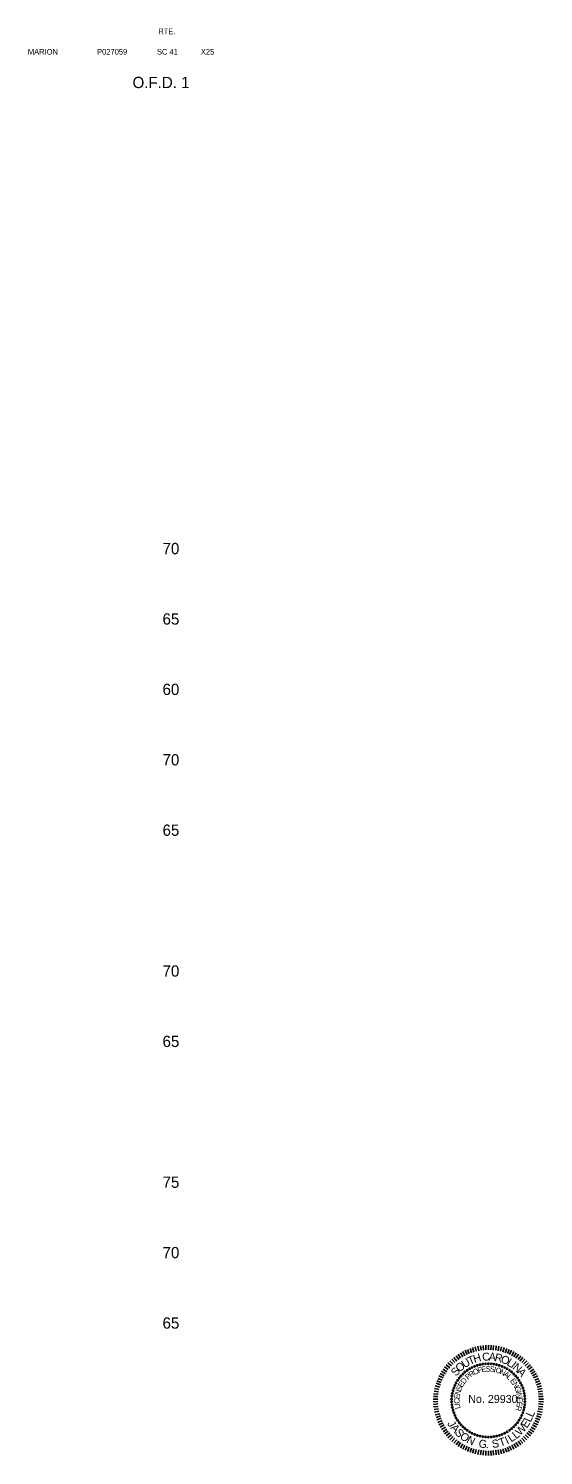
# Model space of a CAD drawing. Extents: x 1001 to 1184, y 1001 to 1102.
# Drawn here: x 1147.4 to 1184, y 1001 to 1102.3 of the extents above; entities that cross this region are included whole.
import ezdxf

# ---------------------------------------------------------------- set-up
doc = ezdxf.new("R2010")
doc.units = 0
for name, color, linetype in [('RD_HC_Cl', 7, 'Continuous'), ('RD_SHT_TX', 7, 'Continuous'), ('RD_TX_PEShield', 7, 'Continuous'), ('RD_XS_TX_Elev_EX', 7, 'Continuous')]:
    doc.layers.add(name, color=color, linetype=linetype)

# ---------------------------------------------------------------- blocks, each defined once
blk = doc.blocks.new('STILLWELL')
at = {"layer": 'RD_TX_PEShield'}
for p, q in [((-21.1, 28.1), (-23, 30.7)), ((-19.7, 29.1), (-21.5, 31.8)), ((-18.2, 30), (-19.9, 32.8)), ((-16.7, 30.8), (-18.2, 33.7)), ((-15.1, 31.6), (-16.5, 34.6)), ((-13.6, 32.3), (-14.8, 35.3)), ((-11.9, 32.9), (-13, 36)), ((-10.3, 33.4), (-11.2, 36.6)), ((-8.6, 33.9), (-9.4, 37.1)), ((-6.9, 34.3), (-7.5, 37.5)), ((-5.2, 34.6), (-5.7, 37.8)), ((-3.5, 34.8), (-3.8, 38)), ((-1.8, 34.9), (-1.9, 38.2)), ((0, 34.9), (0, 38.2)), ((1.7, 34.9), (1.9, 38.2)), ((3.4, 34.8), (3.7, 38)), ((5.2, 34.6), (5.6, 37.8)), ((6.9, 34.3), (7.5, 37.5)), ((8.6, 33.9), (9.3, 37.1)), ((10.2, 33.4), (11.2, 36.6)), ((11.9, 32.9), (13, 36)), ((13.5, 32.3), (14.7, 35.3)), ((15.1, 31.6), (16.5, 34.6)), ((16.6, 30.8), (18.2, 33.7)), ((18.2, 30), (19.8, 32.8)), ((19.6, 29.1), (21.4, 31.8)), ((21.1, 28.1), (23, 30.7)), ((-29.5, 19.4), (-32.2, 21.3)), ((-28.5, 20.9), (-31.1, 22.8)), ((-27.4, 22.2), (-29.9, 24.3)), ((-26.3, 23.5), (-28.7, 25.7)), ((-25.1, 24.7), (-27.4, 27.1)), ((-23.8, 25.9), (-26, 28.4)), ((-22.5, 27), (-24.5, 29.6)), ((22.4, 27), (24.5, 29.6)), ((23.8, 25.9), (25.9, 28.4)), ((25, 24.7), (27.3, 27.1)), ((26.2, 23.5), (28.6, 25.7)), ((27.4, 22.2), (29.9, 24.3)), ((28.5, 20.9), (31.1, 22.8)), ((29.5, 19.4), (32.2, 21.3)), ((-34.1, 10.2), (-37.2, 11.2)), ((-33.6, 11.8), (-36.6, 12.9)), ((-32.9, 13.4), (-35.9, 14.7)), ((-32.2, 15), (-35.1, 16.4)), ((-31.4, 16.5), (-34.2, 18.1)), ((-30.5, 18), (-33.3, 19.7)), ((30.4, 18), (33.2, 19.7)), ((31.3, 16.5), (34.2, 18.1)), ((32.1, 15), (35.1, 16.4)), ((32.9, 13.4), (35.9, 14.7)), ((33.5, 11.8), (36.6, 12.9)), ((34.1, 10.2), (37.2, 11.2)), ((-35.9, -0.1), (-39.2, 0)), ((-35.8, 1.7), (-39.1, 1.9)), ((-35.6, 3.4), (-38.9, 3.8)), ((-35.4, 5.1), (-38.6, 5.7)), ((-35.1, 6.8), (-38.2, 7.5)), ((-34.6, 8.5), (-37.8, 9.4)), ((34.6, 8.5), (37.7, 9.4)), ((35, 6.8), (38.2, 7.5)), ((35.3, 5.1), (38.5, 5.7)), ((35.6, 3.4), (38.8, 3.8)), ((35.7, 1.7), (39, 1.9)), ((35.8, -0.1), (39.1, 0)), ((-35.9, -1.8), (-39.2, -1.9)), ((-35.8, -3.5), (-39.1, -3.8)), ((-35.6, -5.3), (-38.9, -5.6)), ((-35.4, -7), (-38.6, -7.5)), ((-35.1, -8.7), (-38.2, -9.4)), ((35, -8.7), (38.2, -9.4)), ((35.3, -7), (38.5, -7.5)), ((35.6, -5.3), (38.8, -5.6)), ((35.7, -3.5), (39, -3.8)), ((35.8, -1.8), (39.1, -1.9)), ((-34.6, -10.4), (-37.8, -11.2)), ((-34.1, -12), (-37.2, -13)), ((-33.6, -13.6), (-36.6, -14.8)), ((-32.9, -15.3), (-35.9, -16.6)), ((-32.2, -16.8), (-35.1, -18.3)), ((-31.4, -18.4), (-34.2, -19.9)), ((-30.5, -19.9), (-33.3, -21.6)), ((30.4, -19.9), (33.2, -21.6)), ((31.3, -18.4), (34.2, -19.9)), ((32.1, -16.8), (35.1, -18.3)), ((32.9, -15.3), (35.9, -16.6)), ((33.5, -13.6), (36.6, -14.8)), ((34.1, -12), (37.2, -13)), ((34.6, -10.4), (37.7, -11.2)), ((-29.5, -21.3), (-32.2, -23.2)), ((-28.5, -22.7), (-31.1, -24.7)), ((-27.4, -24.1), (-29.9, -26.2)), ((-26.3, -25.4), (-28.7, -27.6)), ((-25.1, -26.6), (-27.4, -28.9)), ((-23.8, -27.8), (-26, -30.2)), ((-22.5, -28.9), (-24.5, -31.4)), ((-21.1, -29.9), (-23, -32.6)), ((21.1, -29.9), (23, -32.6)), ((22.4, -28.9), (24.5, -31.4)), ((23.8, -27.8), (25.9, -30.2)), ((25, -26.6), (27.3, -28.9)), ((26.2, -25.4), (28.6, -27.6)), ((27.4, -24.1), (29.9, -26.2)), ((28.5, -22.7), (31.1, -24.7)), ((29.5, -21.3), (32.2, -23.2)), ((-19.7, -30.9), (-21.5, -33.7)), ((-18.2, -31.8), (-19.9, -34.7)), ((-16.7, -32.7), (-18.2, -35.6)), ((-15.1, -33.5), (-16.5, -36.4)), ((-13.6, -34.1), (-14.8, -37.2)), ((-11.9, -34.8), (-13, -37.8)), ((-10.3, -35.3), (-11.2, -38.4)), ((-8.6, -35.8), (-9.4, -38.9)), ((-6.9, -36.1), (-7.5, -39.3)), ((-5.2, -36.4), (-5.7, -39.7)), ((-3.5, -36.6), (-3.8, -39.9)), ((-1.8, -36.8), (-1.9, -40)), ((0, -36.8), (0, -40.1)), ((1.7, -36.8), (1.9, -40)), ((3.4, -36.6), (3.7, -39.9)), ((5.2, -36.4), (5.6, -39.7)), ((6.9, -36.1), (7.5, -39.3)), ((8.6, -35.8), (9.3, -38.9)), ((10.2, -35.3), (11.2, -38.4)), ((11.9, -34.8), (13, -37.8)), ((13.5, -34.1), (14.7, -37.2)), ((15.1, -33.5), (16.5, -36.4)), ((16.6, -32.7), (18.2, -35.6)), ((18.2, -31.8), (19.8, -34.7)), ((19.6, -30.9), (21.4, -33.7))]:
    blk.add_line(p, q, dxfattribs=at)
for centre in [(-15, 20.4), (-13.3, 21.5), (-11.6, 22.4), (-9.8, 23.2), (-7.9, 23.9), (-6, 24.4), (-4, 24.8), (-2, 25), (0, 25.1), (2, 25), (3.9, 24.8), (5.9, 24.4), (7.8, 23.9), (9.7, 23.2), (11.5, 22.4), (13.3, 21.5), (15, 20.4), (-23.8, 9.7), (-22.9, 11.5), (-21.9, 13.2), (-20.7, 14.9), (-19.5, 16.4), (-18.1, 17.8), (-16.6, 19.2), (16.5, 19.2), (18, 17.8), (19.4, 16.4), (20.7, 14.9), (21.8, 13.2), (22.9, 11.5), (23.7, 9.7), (-26.1, 0.1), (-25.9, 2.1), (-25.6, 4), (-25.1, 6), (-24.5, 7.9), (24.5, 7.9), (25.1, 6), (25.5, 4), (25.8, 2.1), (26, 0.1), (-26.1, -1.9), (-25.9, -3.9), (-25.6, -5.9), (-25.1, -7.8), (-24.5, -9.7), (24.5, -9.7), (25.1, -7.8), (25.5, -5.9), (25.8, -3.9), (26, -1.9), (-23.8, -11.6), (-22.9, -13.4), (-21.9, -15.1), (-20.7, -16.7), (-19.5, -18.3), (-18.1, -19.7), (18, -19.7), (19.4, -18.3), (20.7, -16.7), (21.8, -15.1), (22.9, -13.4), (23.7, -11.6), (-16.6, -21), (-15, -22.2), (-13.3, -23.3), (-11.6, -24.3), (-9.8, -25.1), (-7.9, -25.8), (-6, -26.3), (-4, -26.7), (-2, -26.9), (0, -27), (2, -26.9), (3.9, -26.7), (5.9, -26.3), (7.8, -25.8), (9.7, -25.1), (11.5, -24.3), (13.3, -23.3), (15, -22.2), (16.5, -21)]:
    blk.add_circle(centre, 0.49, dxfattribs=at)
for s, height, rotation, p in [('T', 5.68, 23.5044, (-13.2, 24.1)), ('H', 5.68, 16.1357, (-9.9, 25.6)), ('C', 5.68, 4.076, (-4.2, 27.1)), ('A', 5.68, 355.3651, (0.1, 27.4)), ('R', 5.68, 347.3188, (4.1, 27.1)), ('O', 5.68, 338.6079, (8.3, 26.2)), ('S', 5.68, 49.6435, (-22.9, 15.8)), ('O', 5.68, 41.5972, (-20.4, 18.8)), ('U', 5.68, 32.2152, (-16.9, 21.8)), ('O', 3.92, 24.9735, (-10, 16.9)), ('F', 3.92, 15.9995, (-7.1, 18.3)), ('E', 3.92, 8.9511, (-4.7, 19)), ('S', 3.92, 1.2546, (-1.9, 19.4)), ('S', 3.92, 353.558, (0.8, 19.5)), ('I', 3.92, 345.8615, (3.5, 19.2)), ('O', 3.92, 342.6583, (4.7, 19)), ('N', 3.92, 333.6842, (7.7, 18)), ('L', 5.68, 329.226, (12.6, 24.4)), ('I', 5.68, 322.5218, (15.5, 22.8)), ('N', 5.68, 319.1729, (16.8, 21.8)), ('A', 5.68, 310.4621, (20.1, 19)), ('E', 3.92, 60.2341, (-18.5, 7.9)), ('D', 3.92, 52.5376, (-17.1, 10.3)), ('P', 3.92, 41.0022, (-14.5, 13.5)), ('R', 3.92, 33.3057, (-12.5, 15.3)), ('A', 3.92, 325.3521, (10.4, 16.7)), ('L', 3.92, 317.6555, (12.6, 15.1)), ('E', 3.92, 308.0396, (15.1, 12.8)), ('N', 3.92, 300.343, (16.8, 10.6)), ('C', 3.92, 92.2915, (-20.4, -3.2)), ('E', 3.92, 83.9594, (-20.5, -0.2)), ('N', 3.92, 76.2628, (-20.2, 2.5)), ('S', 3.92, 67.9307, (-19.5, 5.4)), ('G', 3.92, 292.0109, (18.3, 8.1)), ('I', 3.92, 283.0368, (19.5, 5.1)), ('N', 3.92, 279.8336, (19.8, 4)), ('E', 3.92, 271.5014, (20.3, 1.1)), ('I', 3.92, 95.4947, (-20.2, -4.3)), ('L', 3.92, 101.9075, (-19.7, -6.6)), ('R', 3.92, 256.1083, (20.1, -4.4)), ('E', 3.92, 263.8049, (20.4, -1.7)), ('L', 5.68, 65.098, (31.6, -13.3)), ('J', 5.68, 299.033, (-29.4, -17.3)), ('A', 5.68, 310.5887, (-27.2, -20.6)), ('W', 5.68, 47.0518, (22.6, -26.4)), ('E', 5.68, 56.4327, (27.3, -21.1)), ('L', 5.68, 65.098, (30, -16.9)), ('S', 5.68, 310.5887, (-24.3, -24)), ('O', 5.68, 321.0072, (-20.8, -27.4)), ('N', 5.68, 333.4326, (-16, -30.8)), ('G', 5.68, 352.2045, (-7.2, -34.2)), ('S', 5.68, 8.0826, (2.9, -34.8)), ('T', 5.68, 18.9019, (8.5, -33.9)), ('I', 5.68, 25.3991, (13.3, -32.2)), ('L', 5.68, 34.0644, (16.2, -30.9)), ('L', 5.68, 37.6708, (19.6, -28.7)), ('.', 5.68, 0.8698, (-1.8, -34.9))]:
    blk.add_text(s, height=height, rotation=rotation, dxfattribs=at).set_placement(p)
blk.add_text('No. 29930', height=5.68, dxfattribs=at).set_placement((-14.3, -2.8))

msp = doc.modelspace()

# ---------------------------------------------------------------- block references
at = {"layer": 'RD_HC_Cl', "xscale": 0.1, "yscale": 0.10000000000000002}
msp.add_blockref('STILLWELL', (1180.07, 1005), dxfattribs=at)

# ---------------------------------------------------------------- texts
at = {"layer": 'RD_SHT_TX'}
for s, height, p in [('RTE.', 0.4, (1156.62, 1101.93)), ('MARION', 0.4, (1147.35, 1100.48)), ('P027059', 0.4, (1152.27, 1100.48)), ('SC 41', 0.4, (1156.52, 1100.48)), ('X25', 0.4, (1159.64, 1100.48)), ('O.F.D. 1', 0.8, (1154.79, 1098.1))]:
    msp.add_text(s, height=height, dxfattribs=at).set_placement(p)
at = {"layer": 'RD_XS_TX_Elev_EX'}
for s, p in [('70', (1156.92, 1065)), ('65', (1156.92, 1060)), ('60', (1156.92, 1055)), ('70', (1156.92, 1050)), ('65', (1156.92, 1045)), ('70', (1156.92, 1035)), ('65', (1156.92, 1030)), ('75', (1156.92, 1020)), ('70', (1156.92, 1015)), ('65', (1156.92, 1010))]:
    msp.add_text(s, height=0.8, dxfattribs=at).set_placement(p)

doc.saveas('drawing.dxf')
